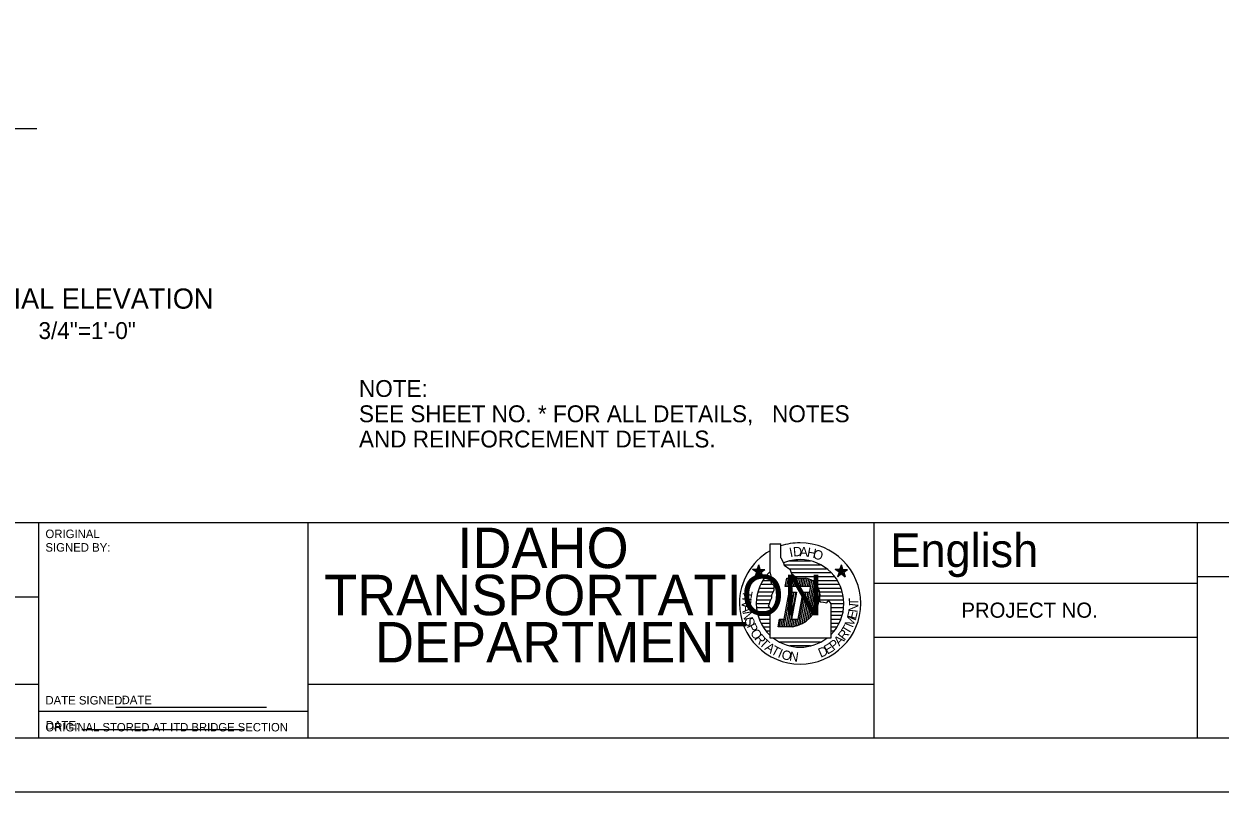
# Model space of a CAD drawing. Extents: x 0 to 22.7, y 0 to 15.8.
# Drawn here: x 7.58 to 14.97, y 0 to 4.75 of the extents above; entities that cross this region are included whole.
import ezdxf

# ---------------------------------------------------------------- set-up
doc = ezdxf.new("R2010")
doc.units = 0
for name, color, linetype in [('BORDER_ANNO_Cutsheet', 7, 'Continuous'), ('BRDG_ANNO_Anno-Large-Print', 7, 'Continuous'), ('BRDG_ANNO_Anno-Sheet', 7, 'Continuous'), ('BRDG_ANNO_Anno-Small-Print', 7, 'Continuous'), ('BRDG_ANNO_General-Notes', 7, 'Continuous'), ('BRDG_BASE_Obj-Line', 7, 'Continuous')]:
    doc.layers.add(name, color=color, linetype=linetype)

msp = doc.modelspace()

# ---------------------------------------------------------------- linework, layer by layer
at = {"layer": 'BORDER_ANNO_Cutsheet'}
msp.add_lwpolyline([(0, 14.6667), (22.6667, 14.6667), (22.6667, 0), (0, 0)], close=True, dxfattribs=at)
at = {"layer": 'BRDG_ANNO_Anno-Large-Print'}
msp.add_line((7.9329, 0.3871), (8.9371, 0.3871), dxfattribs=at)
at = {"layer": 'BRDG_ANNO_Anno-Sheet'}
for p, q in [((1, 1.6667), (12.8333, 1.6667)), ((7.6667, 0.3333), (7.6667, 1.6667)), ((9.3333, 0.3333), (9.3333, 1.6667)), ((12.8333, 0.3333), (12.8333, 1.6667)), ((12.8333, 1.6667), (22.3333, 1.6667)), ((14.8333, 0.3333), (14.8333, 1.6667)), ((12.1896, 1.3617), (12.1896, 1.5354)), ((12.1896, 1.5354), (12.2554, 1.5354)), ((12.2554, 1.4487), (12.2554, 1.5354)), ((12.2554, 1.4487), (12.2729, 1.4175)), ((12.2729, 1.4175), (12.2762, 1.4033)), ((12.31, 1.4296), (12.4387, 1.4296)), ((12.1342, 1.36), (12.0817, 1.3771)), ((12.1104, 1.3771), (12.0817, 1.3771)), ((12.105, 1.36), (12.0817, 1.3771)), ((12.1288, 1.3771), (12.0958, 1.3321)), ((12.105, 1.36), (12.0958, 1.3321)), ((12.1196, 1.3492), (12.0958, 1.3321)), ((12.105, 1.36), (12.1579, 1.3771)), ((12.1104, 1.3771), (12.1196, 1.4046)), ((12.1104, 1.3771), (12.1433, 1.3321)), ((12.1196, 1.3492), (12.1196, 1.4046)), ((12.1288, 1.3771), (12.1196, 1.4046)), ((12.1196, 1.3492), (12.1433, 1.3321)), ((12.1288, 1.3771), (12.1579, 1.3771)), ((12.1342, 1.36), (12.1579, 1.3771)), ((12.1342, 1.36), (12.1433, 1.3321)), ((12.1612, 1.3337), (12.1958, 1.3337)), ((12.1829, 1.3575), (12.1908, 1.3575)), ((12.1962, 1.3375), (12.1896, 1.3617)), ((12.1962, 1.3167), (12.1962, 1.3375)), ((12.2762, 1.4033), (12.3108, 1.3792)), ((12.2779, 1.4054), (12.5004, 1.4054)), ((12.31, 1.3817), (12.5379, 1.3817)), ((12.3108, 1.3792), (12.3217, 1.3513)), ((12.3192, 1.3575), (12.5671, 1.3575)), ((12.3217, 1.3513), (12.3562, 1.3237)), ((12.3438, 1.3337), (12.5883, 1.3337)), ((12.645, 1.36), (12.5921, 1.3771)), ((12.6158, 1.36), (12.5921, 1.3771)), ((12.6212, 1.3771), (12.5921, 1.3771)), ((12.6396, 1.3771), (12.6067, 1.3321)), ((12.6158, 1.36), (12.6067, 1.3321)), ((12.6304, 1.3492), (12.6067, 1.3321)), ((12.6158, 1.36), (12.6683, 1.3771)), ((12.6212, 1.3771), (12.6304, 1.4046)), ((12.6212, 1.3771), (12.6542, 1.3321)), ((12.6304, 1.3492), (12.6304, 1.4046)), ((12.6396, 1.3771), (12.6304, 1.4046)), ((12.6304, 1.3492), (12.6542, 1.3321)), ((12.6396, 1.3771), (12.6683, 1.3771)), ((12.645, 1.36), (12.6683, 1.3771)), ((12.645, 1.36), (12.6542, 1.3321)), ((14.8333, 1.3333), (20.1667, 1.3333)), ((12.1208, 1.2617), (12.2125, 1.2617)), ((12.1312, 1.2854), (12.1988, 1.2854)), ((12.1446, 1.3096), (12.195, 1.3096)), ((12.1962, 1.2992), (12.1962, 1.3167)), ((12.2, 1.2854), (12.1962, 1.2992)), ((12.2137, 1.2783), (12.2, 1.2854)), ((12.2137, 1.2608), (12.2137, 1.2783)), ((12.2137, 1.2504), (12.2137, 1.2608)), ((12.2833, 1.2712), (12.2937, 1.3237)), ((12.4408, 1.2712), (12.2833, 1.2712)), ((12.2929, 1.2712), (12.3025, 1.3237)), ((12.2937, 1.3237), (12.4083, 1.3237)), ((12.3033, 1.2712), (12.3133, 1.3237)), ((12.3142, 1.2712), (12.3238, 1.3237)), ((12.3246, 1.2712), (12.3346, 1.3237)), ((12.335, 1.2712), (12.345, 1.3237)), ((12.3458, 1.2712), (12.3554, 1.3237)), ((12.3562, 1.2712), (12.3662, 1.3237)), ((12.3671, 1.2712), (12.3767, 1.3237)), ((12.3775, 1.2712), (12.3875, 1.3237)), ((12.3883, 1.2712), (12.3979, 1.3237)), ((12.3987, 1.2712), (12.4087, 1.3237)), ((12.3996, 1.0496), (12.4479, 1.3079)), ((12.4092, 1.2712), (12.4187, 1.3208)), ((12.4117, 1.0571), (12.4575, 1.3013)), ((12.42, 1.2712), (12.4287, 1.3179)), ((12.4242, 1.0671), (12.4662, 1.2925)), ((12.4304, 1.2712), (12.4383, 1.3133)), ((12.4346, 1.2367), (12.4408, 1.2712)), ((12.4371, 1.0792), (12.475, 1.2829)), ((12.4458, 1.3096), (12.605, 1.3096)), ((12.4504, 1.0933), (12.4833, 1.2708)), ((12.4733, 1.2854), (12.6183, 1.2854)), ((12.4883, 1.2617), (12.6288, 1.2617)), ((12.8333, 1.2917), (14.8333, 1.2917)), ((6.3333, 1.2083), (7.6667, 1.2083)), ((12.105, 1.1896), (12.1937, 1.1896)), ((12.1083, 1.2137), (12.1988, 1.2137)), ((12.1137, 1.2375), (12.2075, 1.2375)), ((12.1896, 1.1812), (12.2, 1.2021)), ((12.2, 1.2192), (12.2067, 1.2333)), ((12.2, 1.2021), (12.2, 1.2192)), ((12.2067, 1.2333), (12.2137, 1.2504)), ((12.2762, 1.07), (12.3075, 1.2367)), ((12.2775, 1.0212), (12.3179, 1.2367)), ((12.2883, 1.0212), (12.3287, 1.2367)), ((12.2988, 1.0212), (12.3392, 1.2367)), ((12.3075, 1.2367), (12.3533, 1.2367)), ((12.3096, 1.0212), (12.35, 1.2367)), ((12.3533, 1.2367), (12.3221, 1.07)), ((12.3625, 1.07), (12.3937, 1.2367)), ((12.3646, 1.0317), (12.4029, 1.2367)), ((12.3758, 1.0367), (12.4133, 1.2367)), ((12.3875, 1.0421), (12.4242, 1.2367)), ((12.3937, 1.2367), (12.4346, 1.2367)), ((12.4646, 1.1125), (12.4912, 1.2546)), ((12.4812, 1.145), (12.4971, 1.23)), ((12.4938, 1.185), (12.4987, 1.1775)), ((12.495, 1.1896), (12.645, 1.1896)), ((12.4962, 1.2375), (12.6363, 1.2375)), ((12.4983, 1.2137), (12.6417, 1.2137)), ((12.5404, 1.1708), (12.5508, 1.1846)), ((12.5508, 1.1846), (12.5646, 1.1638)), ((12.1042, 1.1654), (12.185, 1.1654)), ((12.1054, 1.1417), (12.1875, 1.1417)), ((12.1087, 1.1175), (12.1988, 1.1175)), ((12.1792, 1.15), (12.1858, 1.1671)), ((12.1896, 1.1396), (12.1792, 1.15)), ((12.1858, 1.1671), (12.1896, 1.1812)), ((12.1962, 1.1292), (12.1896, 1.1396)), ((12.1896, 1.1013), (12.2, 1.1117)), ((12.2, 1.1221), (12.1962, 1.1292)), ((12.2, 1.1117), (12.2, 1.1221)), ((12.4987, 1.1775), (12.5196, 1.1742)), ((12.5196, 1.1742), (12.5404, 1.1708)), ((12.5633, 1.1654), (12.6458, 1.1654)), ((12.5646, 1.1638), (12.5646, 0.9517)), ((12.5646, 1.1175), (12.6412, 1.1175)), ((12.565, 1.1417), (12.6446, 1.1417)), ((12.1142, 1.0938), (12.1892, 1.0938)), ((12.1225, 1.0696), (12.1883, 1.0696)), ((12.1329, 1.0454), (12.1883, 1.0454)), ((12.1896, 0.9517), (12.1896, 1.1013)), ((12.2396, 1.0212), (12.2487, 1.07)), ((12.2458, 1.0212), (12.255, 1.07)), ((12.2487, 1.07), (12.2762, 1.07)), ((12.2567, 1.0212), (12.2658, 1.07)), ((12.2671, 1.0212), (12.2762, 1.07)), ((12.32, 1.0212), (12.3292, 1.07)), ((12.3221, 1.07), (12.3625, 1.07)), ((12.3308, 1.0217), (12.34, 1.07)), ((12.3421, 1.0246), (12.3504, 1.07)), ((12.3533, 1.0279), (12.3608, 1.07)), ((12.5646, 1.0938), (12.6358, 1.0938)), ((12.5646, 1.0696), (12.6275, 1.0696)), ((12.5646, 1.0454), (12.6167, 1.0454)), ((12.1467, 1.0217), (12.1887, 1.0217)), ((12.1638, 0.9975), (12.1883, 0.9975)), ((12.185, 0.9738), (12.1892, 0.9738)), ((12.3283, 1.0212), (12.2396, 1.0212)), ((12.5646, 1.0217), (12.6033, 1.0217)), ((12.5646, 0.9975), (12.5867, 0.9975)), ((12.5646, 0.9517), (12.1896, 0.9517)), ((12.5004, 0.9275), (12.2479, 0.9275)), ((12.4392, 0.9037), (12.3117, 0.9037)), ((12.8333, 0.9583), (14.8333, 0.9583)), ((6.3333, 0.6667), (7.6667, 0.6667)), ((9.3333, 0.6667), (12.8333, 0.6667))]:
    msp.add_line(p, q, dxfattribs=at)
msp.add_lwpolyline([(1, 14.3333), (22.3333, 14.3333), (22.3333, 0.3333), (1, 0.3333)], close=True, dxfattribs=at)
for centre, radius, start, end in [((12.375, 1.1667), 0.375, 119.63312, 180), ((12.375, 1.1667), 0.375, 90, 108.596), ((12.375, 1.1667), 0.375, 0, 90), ((12.375, 1.1667), 0.2708, 90, 112.14518), ((12.375, 1.1667), 0.2708, 0, 90), ((12.375, 1.1667), 0.2708, 133.19257, 180), ((12.3888, 1.2161), 0.1094, 343.49805, 79.73615), ((12.2899, 1.2255), 0.2078, 280.64795, 348.77185), ((12.375, 1.1667), 0.375, 180, 270), ((12.375, 1.1667), 0.2708, 180.26444, 226.79463), ((12.375, 1.1667), 0.375, 270, 0), ((12.375, 1.1667), 0.2708, 314.427, 0), ((12.375, 1.1667), 0.2708, 232.5658, 270), ((12.375, 1.1667), 0.2708, 270, 307.45359)]:
    msp.add_arc(centre, radius, start, end, dxfattribs=at)
at = {"layer": 'BRDG_ANNO_Anno-Small-Print'}
for p, q in [((8.1442, 0.5242), (9.0758, 0.5242)), ((7.6667, 0.5), (9.3333, 0.5))]:
    msp.add_line(p, q, dxfattribs=at)
at = {"layer": 'BRDG_BASE_Obj-Line'}
msp.add_lwpolyline([(7.6544, 4.1021), (6.9933, 4.1021), (6.9693, 4.0118), (6.9452, 4.1923), (6.9212, 4.1021), (6.4044, 4.1021), (5.8875, 4.1021), (5.8635, 4.0118), (5.8395, 4.1923), (5.8154, 4.1021), (5.1544, 4.1021)], dxfattribs=at)

# ---------------------------------------------------------------- texts
at = {"layer": 'BRDG_ANNO_Anno-Large-Print'}
msp.add_text('DATE:', height=0.05248, dxfattribs=at).set_placement((7.71, 0.3871))
at = {"layer": 'BRDG_ANNO_Anno-Sheet'}
for s, height, p in [('IDAHO', 0.25, (10.2558, 1.3854)), ('English', 0.20833, (12.9337, 1.3912)), ('TRANSPORTATION', 0.25, (9.4313, 1.0938)), ('PROJECT NO.', 0.09375, (13.3728, 1.0783)), ('DEPARTMENT', 0.25, (9.7462, 0.8021))]:
    msp.add_text(s, height=height, dxfattribs=at).set_placement(p)
for s, rotation, p in [('I', 11.95188, (12.3146, 1.4521)), ('D', 5.21184, (12.3342, 1.4563)), ('A', 357.8718, (12.3712, 1.4587)), ('H', 349.63177, (12.4146, 1.4558)), ('O', 342.19173, (12.4496, 1.4487)), ('R', 266.0275, (12.0175, 1.205)), ('T', 259.42648, (12.0254, 1.2504)), ('T', 90.49256, (12.7346, 1.1529)), ('A', 273.76404, (12.0154, 1.1604)), ('N', 280.37584, (12.0192, 1.1142)), ('E', 75.61046, (12.7196, 1.0646)), ('N', 83.19321, (12.73, 1.1087)), ('S', 287.92792, (12.0287, 1.0692)), ('P', 295.49755, (12.0437, 1.0271)), ('T', 59.03624, (12.6758, 0.97)), ('M', 67.71394, (12.7004, 1.0137)), ('O', 302.64464, (12.0637, 0.9867)), ('R', 309.90789, (12.0892, 0.9483)), ('A', 45, (12.6171, 0.9004)), ('R', 52.33438, (12.6492, 0.9342)), ('T', 317.1211, (12.1183, 0.9142)), ('A', 324.63754, (12.1521, 0.8837)), ('T', 331.75026, (12.1896, 0.8579)), ('D', 22.98872, (12.5021, 0.8304)), ('E', 30.54757, (12.5437, 0.8492)), ('P', 37.66562, (12.5821, 0.8729)), ('I', 337.0213, (12.2329, 0.8358)), ('O', 343.32869, (12.255, 0.8271)), ('N', 351.65981, (12.3058, 0.8133))]:
    msp.add_text(s, height=0.0579, rotation=rotation, dxfattribs=at).set_placement(p)
at = {"layer": 'BRDG_ANNO_Anno-Small-Print'}
for s, height, p in [('ORIGINAL', 0.0525, (7.7083, 1.5708)), ('SIGNED BY:', 0.0525, (7.7083, 1.4871)), ('DATE SIGNED:', 0.0525, (7.7083, 0.5417)), ('DATE', 0.05248, (8.1792, 0.5437)), ('ORIGINAL STORED AT ITD BRIDGE SECTION', 0.052144, (7.7083, 0.3752))]:
    msp.add_text(s, height=height, dxfattribs=at).set_placement(p)
at = {"layer": 'BRDG_ANNO_General-Notes'}
for s, height, p in [('PARTIAL ELEVATION', 0.125, (7.0656, 2.9897)), ('3/4"=1\'-0"', 0.10417, (7.6653, 2.8022)), ('NOTE:', 0.10417, (9.6471, 2.444)), ('SEE SHEET NO. * FOR ALL DETAILS,   NOTES', 0.104167, (9.6471, 2.2877)), ('AND REINFORCEMENT DETAILS.', 0.104167, (9.6471, 2.1315))]:
    msp.add_text(s, height=height, dxfattribs=at).set_placement(p)

doc.saveas('drawing.dxf')
